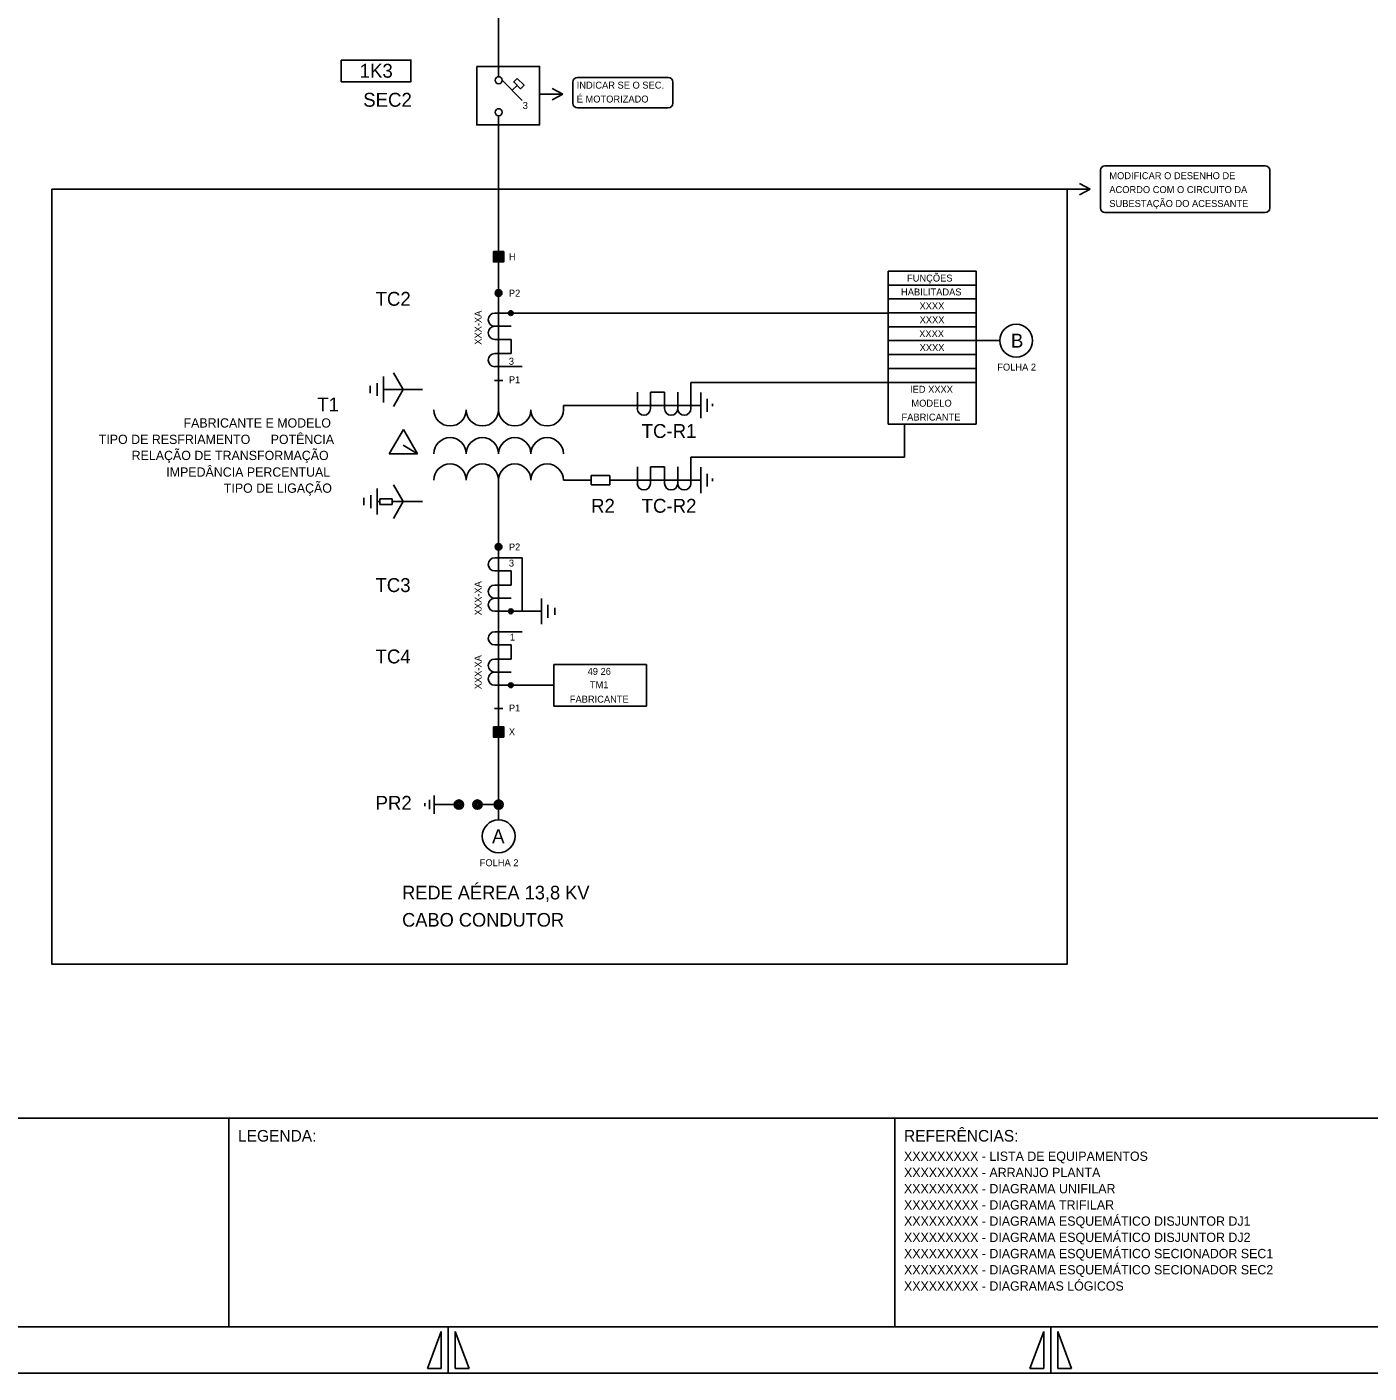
# Model space of a CAD drawing. Extents: x 563 to 1404, y 358 to 952.
# Drawn here: x 812.7 to 1102.2, y 358 to 648.4 of the extents above; entities that cross this region are included whole.
import ezdxf

# ---------------------------------------------------------------- set-up
doc = ezdxf.new("R2010")
doc.units = 0
doc.layers.add('New Level (0)', color=7, linetype='Continuous')

msp = doc.modelspace()

# ---------------------------------------------------------------- linework, layer by layer
for p, q in [((914.46, 705.43), (914.46, 637.7)), ((919.56, 632.59), (915.22, 636.93)), ((918.45, 635.82), (917.39, 634.76)), ((914.46, 629.26), (914.46, 614.76)), ((914.46, 565.81), (914.46, 614.76)), ((913.34, 597.79), (915.49, 599.94)), ((913.34, 597.96), (915.32, 599.94)), ((913.34, 598.14), (915.14, 599.94)), ((913.34, 598.32), (914.96, 599.94)), ((913.34, 598.49), (914.79, 599.94)), ((913.34, 598.67), (914.61, 599.94)), ((913.34, 598.85), (914.43, 599.94)), ((913.34, 599.02), (914.26, 599.94)), ((913.34, 599.2), (914.08, 599.94)), ((913.34, 599.38), (913.9, 599.94)), ((913.34, 599.55), (913.73, 599.94)), ((913.34, 599.73), (913.55, 599.94)), ((913.34, 599.91), (913.37, 599.94)), ((913.46, 597.73), (915.55, 599.82)), ((913.64, 597.73), (915.55, 599.64)), ((913.81, 597.73), (915.55, 599.47)), ((913.99, 597.73), (915.55, 599.29)), ((914.17, 597.73), (915.55, 599.11)), ((914.34, 597.73), (915.55, 598.94)), ((914.52, 597.73), (915.55, 598.76)), ((914.7, 597.73), (915.55, 598.58)), ((914.87, 597.73), (915.55, 598.41)), ((915.05, 597.73), (915.55, 598.23)), ((915.23, 597.73), (915.55, 598.05)), ((915.4, 597.73), (915.55, 597.88)), ((998.51, 595.74), (998.51, 562.74)), ((1017.49, 595.74), (998.51, 595.74)), ((1017.49, 595.74), (1017.49, 562.74)), ((1017.49, 592.74), (998.51, 592.74)), ((1017.49, 589.74), (998.51, 589.74)), ((913.64, 586.67), (998.51, 586.67)), ((1017.49, 586.74), (998.51, 586.74)), ((913.64, 583.84), (917.18, 583.84)), ((913.64, 581.01), (917.18, 581.01)), ((917.18, 577.96), (917.18, 581.01)), ((1017.49, 583.74), (998.51, 583.74)), ((1022.57, 580.74), (998.51, 580.74)), ((913.64, 577.96), (917.18, 577.96)), ((1017.49, 577.74), (998.51, 577.74)), ((1017.49, 577.74), (998.51, 577.74)), ((889.65, 567.4), (889.65, 572.99)), ((893.84, 570.19), (891.75, 573.82)), ((913.64, 575.13), (919.51, 575.13)), ((1017.49, 574.74), (998.51, 574.74)), ((886.77, 569.41), (886.77, 570.97)), ((888.25, 571.59), (888.25, 568.8)), ((898.03, 570.19), (889.65, 570.19)), ((893.84, 570.19), (891.75, 566.56)), ((944.39, 566.07), (944.39, 569.61)), ((947.22, 569.61), (950.27, 569.61)), ((947.22, 566.07), (947.22, 569.61)), ((950.27, 566.07), (950.27, 569.61)), ((953.1, 566.07), (953.1, 569.61)), ((955.93, 566.07), (955.93, 571.74)), ((955.93, 571.74), (998.51, 571.74)), ((958.05, 569.56), (958.05, 563.98)), ((1017.49, 571.74), (998.51, 571.74)), ((928.42, 566.77), (958.05, 566.77)), ((928.42, 565.81), (928.42, 566.77)), ((959.44, 565.37), (959.44, 568.17)), ((960.61, 567.11), (960.61, 566.57)), ((890.88, 556.32), (893.91, 561.56)), ((893.91, 561.56), (896.93, 556.32)), ((1017.49, 562.74), (998.51, 562.74)), ((1002.01, 562.74), (1002.01, 555.6)), ((896.93, 556.32), (893.84, 558.19)), ((896.93, 556.32), (890.88, 556.32)), ((955.93, 549.94), (955.93, 555.6)), ((955.93, 555.6), (1002.01, 555.6)), ((944.39, 549.94), (944.39, 553.48)), ((947.22, 553.48), (950.27, 553.48)), ((947.22, 549.94), (947.22, 553.48)), ((950.27, 549.94), (950.27, 553.48)), ((953.1, 549.94), (953.1, 553.48)), ((958.05, 553.43), (958.05, 547.84)), ((959.44, 549.24), (959.44, 552.03)), ((893.84, 546.02), (891.75, 549.65)), ((928.42, 550.64), (934.39, 550.64)), ((934.39, 549.63), (934.39, 551.65)), ((938.42, 551.65), (934.39, 551.65)), ((938.42, 549.63), (934.39, 549.63)), ((938.42, 549.63), (938.42, 551.65)), ((938.42, 550.64), (958.05, 550.64)), ((960.61, 550.98), (960.61, 550.44)), ((885.38, 545.24), (885.38, 546.8)), ((886.86, 547.42), (886.86, 544.62)), ((888.25, 543.23), (888.25, 548.81)), ((888.83, 546.02), (888.25, 546.02)), ((898.03, 546.02), (891.52, 546.02)), ((893.84, 546.02), (891.75, 542.39)), ((913.64, 533.87), (919.51, 533.87)), ((913.64, 531.04), (917.18, 531.04)), ((917.18, 531.04), (917.18, 527.99)), ((913.64, 527.99), (917.18, 527.99)), ((913.64, 525.16), (917.18, 525.16)), ((923.7, 519.54), (923.7, 525.12)), ((925.1, 523.73), (925.1, 520.93)), ((926.58, 521.55), (926.58, 523.11)), ((913.64, 522.33), (917.18, 522.33)), ((917.18, 522.33), (923.7, 522.33)), ((913.64, 517.91), (919.51, 517.91)), ((913.64, 515.08), (917.18, 515.08)), ((917.18, 515.08), (917.18, 512.03)), ((913.64, 512.03), (917.18, 512.03)), ((913.64, 509.2), (917.18, 509.2)), ((926.38, 510.87), (926.38, 501.87)), ((926.38, 510.87), (946.37, 510.87)), ((946.37, 510.87), (946.37, 501.87)), ((913.64, 506.37), (926.38, 506.37)), ((913.64, 506.37), (917.18, 506.37)), ((926.38, 501.87), (946.37, 501.87)), ((913.34, 495.27), (915.49, 497.42)), ((913.34, 495.44), (915.32, 497.42)), ((913.34, 495.62), (915.14, 497.42)), ((913.34, 495.8), (914.96, 497.42)), ((913.34, 495.97), (914.79, 497.42)), ((913.34, 496.15), (914.61, 497.42)), ((913.34, 496.33), (914.43, 497.42)), ((913.34, 496.5), (914.26, 497.42)), ((913.34, 496.68), (914.08, 497.42)), ((913.34, 496.86), (913.9, 497.42)), ((913.34, 497.04), (913.73, 497.42)), ((913.34, 497.21), (913.55, 497.42)), ((913.34, 497.39), (913.37, 497.42)), ((913.46, 495.21), (915.55, 497.3)), ((913.64, 495.21), (915.55, 497.12)), ((913.81, 495.21), (915.55, 496.95)), ((913.99, 495.21), (915.55, 496.77)), ((914.17, 495.21), (915.55, 496.59)), ((914.34, 495.21), (915.55, 496.42)), ((914.52, 495.21), (915.55, 496.24)), ((914.7, 495.21), (915.55, 496.06)), ((914.87, 495.21), (915.55, 495.89)), ((915.05, 495.21), (915.55, 495.71)), ((915.23, 495.21), (915.55, 495.53)), ((915.4, 495.21), (915.55, 495.36)), ((900.57, 478.62), (900.57, 482.62)), ((898.57, 480.92), (898.57, 480.32)), ((898.57, 480.62), (898.57, 480.62)), ((899.57, 481.62), (899.57, 479.62)), ((901.89, 480.62), (900.57, 480.62)), ((905.89, 480.62), (901.89, 480.62)), ((914.47, 480.62), (909.89, 480.62))]:
    msp.add_line(p, q)
for points in [[(918.48, 637.33), (917.72, 636.56), (919.19, 635.08), (919.96, 635.85)], [(913.34, 599.94), (915.55, 599.94), (915.55, 597.73), (913.34, 597.73)], [(913.34, 497.42), (915.55, 497.42), (915.55, 495.21), (913.34, 495.21)]]:
    msp.add_lwpolyline(points, close=True)
for centre, radius in [((914.46, 636.93), 0.768), ((914.46, 630.02), 0.768), ((914.45, 591.01), 0.729), ((914.46, 591), 0.511), ((914.46, 591), 0.288), ((917.09, 586.67), 0.511), ((917.09, 586.67), 0.288), ((914.45, 536.24), 0.729), ((914.46, 536.24), 0.511), ((914.46, 536.24), 0.288), ((917.1, 522.33), 0.511), ((917.1, 522.33), 0.288), ((917.09, 506.37), 0.511), ((917.09, 506.37), 0.288), ((905.89, 480.62), 1), ((905.89, 480.62), 0.75), ((905.89, 480.62), 0.5), ((905.89, 480.62), 0.25), ((909.89, 480.62), 1), ((909.89, 480.62), 0.75), ((909.89, 480.62), 0.5), ((909.89, 480.62), 0.25), ((914.47, 480.62), 1), ((914.47, 480.62), 0.75), ((914.47, 480.62), 0.5), ((914.47, 480.62), 0.25)]:
    msp.add_circle(centre, radius)
for centre, radius, start, end in [((913.64, 585.26), 1.42, 90, 270), ((913.64, 582.43), 1.42, 90, 270), ((913.64, 576.54), 1.42, 90, 270), ((903.98, 565.81), 3.49, 180, 0), ((910.96, 565.81), 3.49, 180, 0), ((917.95, 565.81), 3.49, 180, 0), ((924.93, 565.81), 3.49, 180, 0), ((945.8, 566.07), 1.42, 180, 0), ((951.68, 566.07), 1.42, 180, 0), ((954.51, 566.07), 1.42, 180, 0), ((903.98, 556.32), 3.49, 0, 180), ((910.96, 556.32), 3.49, 0, 180), ((917.95, 556.32), 3.49, 0, 180), ((924.93, 556.32), 3.49, 0, 180), ((903.98, 550.64), 3.49, 0, 180), ((910.96, 550.64), 3.49, 0, 180), ((917.95, 550.64), 3.49, 0, 180), ((924.93, 550.64), 3.49, 0, 180), ((945.8, 549.94), 1.42, 180, 0), ((951.68, 549.94), 1.42, 180, 0), ((954.51, 549.94), 1.42, 180, 0), ((913.64, 532.46), 1.42, 90, 270), ((913.64, 526.58), 1.42, 90, 270), ((913.64, 523.75), 1.42, 90, 270), ((913.64, 516.5), 1.42, 90, 270), ((913.64, 510.62), 1.42, 90, 270), ((913.64, 507.79), 1.42, 90, 270)]:
    msp.add_arc(centre, radius, start, end)
at = {"layer": 'New Level (0)'}
for p, q in [((930.48, 631.97), (930.48, 636.52)), ((931.48, 637.52), (938.83, 637.52)), ((938.83, 637.52), (951.06, 637.52)), ((952.06, 636.52), (952.06, 631.97)), ((923.29, 633.92), (928.32, 633.92)), ((928.32, 633.92), (926.02, 635.13)), ((928.32, 633.92), (926.02, 632.71)), ((951.06, 630.97), (931.48, 630.97)), ((1044.27, 609.37), (1044.27, 617.49)), ((1045.27, 618.49), (1052.62, 618.49)), ((1052.62, 618.49), (1079.81, 618.49)), ((1080.81, 617.49), (1080.81, 609.37)), ((1037.08, 613.43), (1042.11, 613.43)), ((1042.11, 613.43), (1039.81, 614.64)), ((1042.11, 613.43), (1039.81, 612.22)), ((1079.81, 608.37), (1045.27, 608.37)), ((913.56, 572.17), (915.36, 572.17)), ((914.46, 550.64), (914.46, 477.34)), ((888.83, 546.02), (888.83, 546.63)), ((888.83, 546.63), (891.52, 546.63)), ((891.52, 545.41), (891.52, 546.63)), ((888.83, 545.41), (888.83, 546.02)), ((888.83, 545.41), (891.52, 545.41)), ((919.51, 522.33), (919.51, 533.87)), ((913.56, 501.35), (915.36, 501.35)), ((572.58, 412.96), (1393.58, 412.96)), ((856.24, 412.96), (856.24, 367.96)), ((999.91, 412.96), (999.91, 367.96)), ((572.58, 367.96), (1393.58, 367.96)), ((572.58, 367.96), (1393.58, 367.96)), ((899.08, 358.96), (902.08, 366.96)), ((902.08, 366.96), (902.08, 358.96)), ((903.58, 367.96), (903.58, 357.96)), ((905.08, 366.96), (905.08, 358.96)), ((908.08, 358.96), (905.08, 366.96)), ((1029.08, 358.96), (1032.08, 366.96)), ((1032.08, 366.96), (1032.08, 358.96)), ((1033.58, 367.96), (1033.58, 357.96)), ((1035.08, 366.96), (1035.08, 358.96)), ((1038.08, 358.96), (1035.08, 366.96)), ((562.58, 357.96), (1403.58, 357.96)), ((562.58, 357.96), (1403.58, 357.96)), ((902.08, 358.96), (899.08, 358.96)), ((905.08, 358.96), (908.08, 358.96)), ((1032.08, 358.96), (1029.08, 358.96)), ((1035.08, 358.96), (1038.08, 358.96))]:
    msp.add_line(p, q, dxfattribs=at)
for points in [[(880.5, 641.29), (895.52, 641.29), (895.52, 636.61), (880.5, 636.61)], [(909.73, 639.92), (923.29, 639.92), (923.29, 627.28), (909.73, 627.28)], [(818.09, 613.43), (1037.08, 613.43), (1037.08, 446.19), (818.09, 446.19)]]:
    msp.add_lwpolyline(points, close=True, dxfattribs=at)
for centre in [(1026.11, 580.74), (914.46, 473.79)]:
    msp.add_circle(centre, 3.54, dxfattribs=at)
for centre, start, end in [((931.48, 636.52), 90, 180), ((951.06, 636.52), 0, 90), ((931.48, 631.97), 180, 270), ((951.06, 631.97), 270, 0), ((1045.27, 617.49), 90, 180), ((1079.81, 617.49), 0, 90), ((1045.27, 609.37), 180, 270), ((1079.81, 609.37), 270, 0)]:
    msp.add_arc(centre, 1, start, end, dxfattribs=at)

# ---------------------------------------------------------------- texts
for s, height, p in [('1K3', 3, (884.49, 637.47)), ('INDICAR SE O SEC. ', 1.5, (931.31, 635.12)), ('SEC2', 3, (885.25, 631.21)), ('É MOTORIZADO', 1.5, (931.31, 632.12)), ('3', 1.5, (919.65, 630.73)), ('MODIFICAR O DESENHO DE ', 1.5, (1046.21, 615.58)), ('ACORDO COM O CIRCUITO DA ', 1.5, (1046.21, 612.58)), ('SUBESTAÇÃO DO ACESSANTE', 1.5, (1046.21, 609.58)), ('H', 1.5, (916.67, 598.09)), ('FUNÇÕES ', 1.5, (1002.57, 593.49)), ('TC2', 3, (887.92, 588.26)), ('P2', 1.5, (916.67, 590.23)), ('HABILITADAS', 1.5, (1001.28, 590.49)), ('XXXX', 1.5, (1005.26, 587.49)), ('XXXX', 1.5, (1005.29, 584.49)), ('XXXX', 1.5, (1005.19, 581.49)), ('B', 3, (1024.98, 579.24)), ('XXXX', 1.5, (1005.29, 578.49)), ('3', 1.5, (916.66, 575.53)), ('FOLHA 2', 1.5, (1022.04, 574.28)), ('P1', 1.5, (916.67, 571.55)), ('IED XXXX', 1.5, (1003.22, 569.49)), ('T1', 3, (875.33, 565.45)), ('MODELO', 1.5, (1003.51, 566.49)), ('FABRICANTE E MODELO', 2, (846.48, 561.98)), ('FABRICANTE', 1.5, (1001.38, 563.49)), ('POTÊNCIA', 2, (865.28, 558.44)), ('TC-R1', 3, (945.32, 559.74)), ('TIPO DE RESFRIAMENTO ', 2, (828.2, 558.44)), ('RELAÇÃO DE TRANSFORMAÇÃO', 2, (835.29, 554.97)), ('IMPEDÂNCIA PERCENTUAL', 2, (842.76, 551.38)), ('TIPO DE LIGAÇÃO', 2, (855.17, 547.91)), ('R2', 3, (934.4, 543.6)), ('TC-R2', 3, (945.32, 543.6)), ('P2', 1.5, (916.67, 535.46)), ('3', 1.5, (916.67, 531.99)), ('TC3', 3, (887.89, 526.49)), ('1', 1.5, (916.88, 516.02)), ('TC4', 3, (887.91, 511.09)), ('49 26', 1.5, (933.66, 508.62)), ('TM1', 1.5, (934.14, 505.73)), ('FABRICANTE', 1.5, (929.82, 502.62)), ('P1', 1.5, (916.67, 500.72)), ('X', 1.5, (916.67, 495.57)), ('PR2', 3, (887.91, 479.5)), ('A', 3, (913.05, 472.29)), ('FOLHA 2', 1.5, (910.38, 467.33)), ('REDE AÉREA 13,8 KV', 2.94, (893.64, 460.17)), ('CABO CONDUTOR ', 2.94, (893.64, 454.29))]:
    msp.add_text(s, height=height).set_placement(p)
for p in [(910.77, 579.85), (910.77, 521.47), (910.77, 505.51)]:
    msp.add_text('XXX-XA', height=1.5, rotation=90).set_placement(p)
for s, height, p in [('LEGENDA:', 2.5, (858.24, 407.91)), ('REFERÊNCIAS:', 2.5, (1001.91, 407.91)), ('XXXXXXXXX - LISTA DE EQUIPAMENTOS', 2, (1001.91, 403.75)), ('XXXXXXXXX - ARRANJO PLANTA', 2, (1001.91, 400.25)), ('XXXXXXXXX - DIAGRAMA UNIFILAR', 2, (1001.91, 396.75)), ('XXXXXXXXX - DIAGRAMA TRIFILAR', 2, (1001.91, 393.25)), ('XXXXXXXXX - DIAGRAMA ESQUEMÁTICO DISJUNTOR DJ1', 2, (1001.91, 389.75)), ('XXXXXXXXX - DIAGRAMA ESQUEMÁTICO DISJUNTOR DJ2', 2, (1001.91, 386.25)), ('XXXXXXXXX - DIAGRAMA ESQUEMÁTICO SECIONADOR SEC1', 2, (1001.91, 382.75)), ('XXXXXXXXX - DIAGRAMA ESQUEMÁTICO SECIONADOR SEC2', 2, (1001.91, 379.25)), ('XXXXXXXXX - DIAGRAMAS LÓGICOS', 2, (1001.91, 375.75))]:
    msp.add_text(s, height=height, dxfattribs=at).set_placement(p)

doc.saveas('drawing.dxf')
